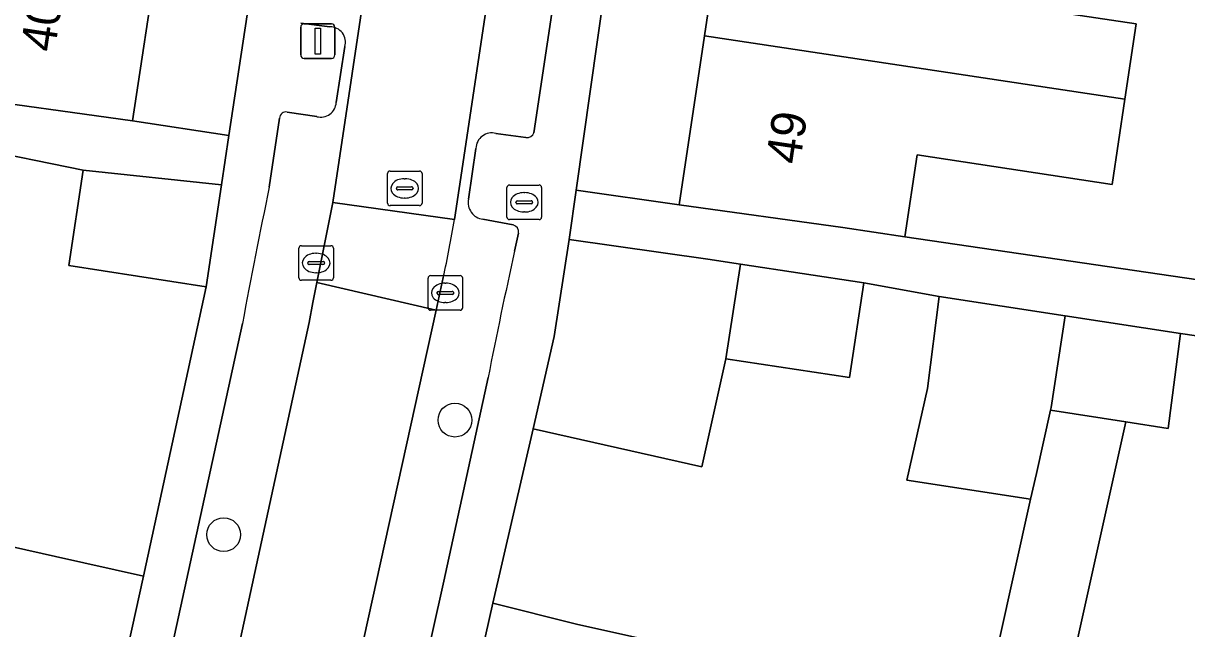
# Model space of a CAD drawing. Extents: x 162172 to 163187, y 382874 to 383685.
# Drawn here: x 163018.49 to 163052.14, y 383120.38 to 383137.87 of the extents above; entities that cross this region are included whole.
import ezdxf

# ---------------------------------------------------------------- set-up
doc = ezdxf.new("R2010")
doc.units = 0
for name, color, linetype in [('IMGEO_Boom', 7, 'Continuous'), ('IMGEO_Brandkraan', 7, 'Continuous'), ('IMGEO_Erf', 7, 'Continuous'), ('IMGEO_Kolk', 7, 'Continuous'), ('IMGEO_Lichtmast', 7, 'Continuous'), ('IMGEO_Muur', 7, 'Continuous'), ('IMGEO_Pand', 7, 'Continuous'), ('IMGEO_Pand_nummerreeks', 7, 'Continuous'), ('IMGEO_Parkeervlak_open', 7, 'Continuous'), ('IMGEO_Rijbaan_lokaal_open', 7, 'Continuous'), ('IMGEO_Rioolput', 7, 'Continuous'), ('IMGEO_Voetpad_open', 7, 'Continuous')]:
    doc.layers.add(name, color=color, linetype=linetype)

msp = doc.modelspace()

# ---------------------------------------------------------------- linework, layer by layer
at = {"layer": 'IMGEO_Boom'}
for centre in [(163030.975, 383126.407), (163024.288, 383123.097)]:
    msp.add_circle(centre, 0.489, dxfattribs=at)
at = {"layer": 'IMGEO_Brandkraan'}
for p, q in [((163032.479, 383132.274), (163032.479, 383133.126)), ((163032.554, 383133.2), (163033.406, 383133.2)), ((163032.967, 383132.98), (163032.992, 383132.98)), ((163033.48, 383133.126), (163033.48, 383132.274)), ((163032.738, 383132.694), (163032.738, 383132.706)), ((163033.176, 383132.657), (163032.778, 383132.657)), ((163032.781, 383132.743), (163033.179, 383132.743)), ((163033.222, 383132.706), (163033.222, 383132.694)), ((163032.99, 383132.42), (163032.965, 383132.42)), ((163033.406, 383132.2), (163032.554, 383132.2))]:
    msp.add_line(p, q, dxfattribs=at)
for points in [[(163032.479, 383132.274), (163032.479, 383133.126)], [(163032.554, 383133.2), (163033.406, 383133.2)], [(163033.48, 383133.126), (163033.48, 383132.274)], [(163033.406, 383132.2), (163032.554, 383132.2)]]:
    msp.add_lwpolyline(points, dxfattribs=at)
for centre, radius, start, end in [((163032.556, 383133.124), 0.0765, 91.552, 178.448), ((163032.556, 383133.124), 0.0765, 91.552, 178.448), ((163033.404, 383133.124), 0.0765, 1.552, 88.448), ((163033.404, 383133.124), 0.0765, 1.552, 88.448), ((163032.778, 383132.703), 0.0403, 85.8775, 175.7526), ((163032.775, 383132.693), 0.0366, 178.938, 274.7102), ((163033.179, 383132.7), 0.043, 264.8664, 352.4533), ((163033.183, 383132.705), 0.0386, 1.7309, 96.639), ((163032.556, 383132.276), 0.0765, 181.552, 268.448), ((163032.556, 383132.276), 0.0765, 181.552, 268.448), ((163033.404, 383132.276), 0.0765, 271.552, 358.448), ((163033.404, 383132.276), 0.0765, 271.552, 358.448)]:
    msp.add_arc(centre, radius, start, end, dxfattribs=at)
for centre, major_axis, ratio, start_param, end_param in [((163032.966, 383132.7), (-0.387, 0.002), 0.722429, 4.712389, 7.853982), ((163032.991, 383132.7), (-0.39, 0.002), 0.717154, 1.570796, 4.712389)]:
    msp.add_ellipse(centre, major_axis=major_axis, ratio=ratio, start_param=start_param, end_param=end_param, dxfattribs=at)
at = {"layer": 'IMGEO_Erf'}
for points in [[(163039.037, 383230.674), (163036.097, 383231.121), (163035.35, 383226.153), (163034.641, 383221.439), (163033.933, 383216.725), (163033.224, 383212.011), (163032.515, 383207.297), (163031.806, 383202.583), (163031.098, 383197.869), (163030.389, 383193.155), (163029.68, 383188.442), (163028.748, 383182.244), (163028.04, 383177.53), (163027.331, 383172.817), (163026.622, 383168.103), (163025.913, 383163.389), (163025.205, 383158.674), (163024.496, 383153.961), (163023.787, 383149.247), (163023.078, 383144.532), (163022.37, 383139.819), (163021.653, 383135.053), (163024.437, 383134.63)], [(163047.622, 383124.122), (163044.042, 383124.672), (163044.637, 383127.317), (163044.981, 383129.981), (163042.797, 383130.377), (163042.384, 383127.642), (163038.812, 383128.181), (163038.11, 383125.06), (163033.233, 383126.158), (163032.072, 383121.12), (163034.487, 383120.513), (163036.871, 383119.984), (163039.136, 383119.482), (163037.909, 383113.95), (163040.271, 383113.426), (163041.077, 383117.068), (163043.222, 383116.593), (163043.641, 383118.483), (163046.121, 383117.933), (163046.242, 383117.906)], [(163056.356, 383120.39), (163056.667, 383122.937), (163057.043, 383122.891), (163057.448, 383125.312), (163053.935, 383125.826), (163054.391, 383128.555), (163051.953, 383128.911), (163051.599, 383126.167), (163050.37, 383126.356), (163049.947, 383124.452), (163048.389, 383117.431), (163047.161, 383111.899), (163049.522, 383111.376), (163051.755, 383110.881), (163052.984, 383116.412), (163053.364, 383118.123), (163055.75, 383117.593)]]:
    msp.add_lwpolyline(points, close=True, dxfattribs=at)
for points in [[(163037.149, 383151.861), (163034.477, 383133.054), (163037.462, 383132.63), (163038.189, 383137.51), (163038.89, 383142.22)], [(163045.037, 383138.705), (163050.673, 383137.856), (163050.346, 383135.679), (163049.976, 383133.218), (163044.339, 383134.068), (163043.983, 383131.701), (163057.99, 383129.648), (163058.091, 383130.579), (163055.442, 383130.893), (163055.877, 383134.562), (163058.943, 383134.199), (163059.146, 383135.906), (163056.419, 383136.285), (163056.859, 383139.456)], [(163016.924, 383123.028), (163019.425, 383122.469), (163021.966, 383121.901), (163023.786, 383130.253), (163019.809, 383130.877), (163020.226, 383133.633), (163017.008, 383134.284)]]:
    msp.add_lwpolyline(points, dxfattribs=at)
at = {"layer": 'IMGEO_Kolk'}
for p, q in [((163026.462, 383130.52), (163026.462, 383131.372)), ((163026.537, 383131.446), (163027.389, 383131.446)), ((163027.463, 383131.372), (163027.463, 383130.52)), ((163026.721, 383130.94), (163026.721, 383130.952)), ((163026.764, 383130.989), (163027.162, 383130.989)), ((163026.95, 383131.226), (163026.975, 383131.226)), ((163027.205, 383130.952), (163027.205, 383130.94)), ((163027.159, 383130.903), (163026.761, 383130.903)), ((163026.973, 383130.666), (163026.948, 383130.666)), ((163030.272, 383130.582), (163031.124, 383130.582)), ((163027.389, 383130.446), (163026.537, 383130.446)), ((163030.197, 383129.656), (163030.197, 383130.508)), ((163030.685, 383130.362), (163030.71, 383130.362)), ((163031.198, 383130.508), (163031.198, 383129.656)), ((163030.456, 383130.076), (163030.456, 383130.088)), ((163030.894, 383130.039), (163030.496, 383130.039)), ((163030.499, 383130.125), (163030.897, 383130.125)), ((163030.94, 383130.088), (163030.94, 383130.076)), ((163031.124, 383129.582), (163030.272, 383129.582)), ((163030.708, 383129.802), (163030.683, 383129.802))]:
    msp.add_line(p, q, dxfattribs=at)
for points in [[(163026.462, 383130.52), (163026.462, 383131.372)], [(163026.537, 383131.446), (163027.389, 383131.446)], [(163027.463, 383131.372), (163027.463, 383130.52)], [(163030.272, 383130.582), (163031.124, 383130.582)], [(163027.389, 383130.446), (163026.537, 383130.446)], [(163030.197, 383129.656), (163030.197, 383130.508)], [(163031.198, 383130.508), (163031.198, 383129.656)], [(163031.124, 383129.582), (163030.272, 383129.582)]]:
    msp.add_lwpolyline(points, dxfattribs=at)
for centre, radius, start, end in [((163026.539, 383131.37), 0.0765, 91.552, 178.448), ((163026.539, 383131.37), 0.0765, 91.552, 178.448), ((163027.387, 383131.37), 0.0765, 1.552, 88.448), ((163027.387, 383131.37), 0.0765, 1.552, 88.448), ((163026.761, 383130.949), 0.0403, 85.8775, 175.7526), ((163026.758, 383130.939), 0.0366, 178.938, 274.7102), ((163027.162, 383130.946), 0.043, 264.8664, 352.4533), ((163027.166, 383130.951), 0.0386, 1.7309, 96.639), ((163030.274, 383130.506), 0.0765, 91.552, 178.448), ((163030.274, 383130.506), 0.0765, 91.552, 178.448), ((163031.122, 383130.506), 0.0765, 1.552, 88.448), ((163031.122, 383130.506), 0.0765, 1.552, 88.448), ((163026.539, 383130.522), 0.0765, 181.552, 268.448), ((163026.539, 383130.522), 0.0765, 181.552, 268.448), ((163027.387, 383130.522), 0.0765, 271.552, 358.448), ((163027.387, 383130.522), 0.0765, 271.552, 358.448), ((163030.496, 383130.085), 0.0403, 85.8775, 175.7526), ((163030.493, 383130.075), 0.0366, 178.938, 274.7102), ((163030.897, 383130.082), 0.043, 264.8664, 352.4533), ((163030.901, 383130.087), 0.0386, 1.7309, 96.639), ((163030.274, 383129.658), 0.0765, 181.552, 268.448), ((163030.274, 383129.658), 0.0765, 181.552, 268.448), ((163031.122, 383129.658), 0.0765, 271.552, 358.448), ((163031.122, 383129.658), 0.0765, 271.552, 358.448)]:
    msp.add_arc(centre, radius, start, end, dxfattribs=at)
for centre, major_axis, ratio, start_param, end_param in [((163026.949, 383130.946), (-0.387, 0.002), 0.722429, 4.712389, 7.853982), ((163026.974, 383130.946), (-0.39, 0.002), 0.717154, 1.570796, 4.712389), ((163030.684, 383130.082), (-0.387, 0.002), 0.722429, 4.712389, 7.853982), ((163030.709, 383130.082), (-0.39, 0.002), 0.717154, 1.570796, 4.712389)]:
    msp.add_ellipse(centre, major_axis=major_axis, ratio=ratio, start_param=start_param, end_param=end_param, dxfattribs=at)
at = {"layer": 'IMGEO_Lichtmast'}
for p, q in [((163026.515, 383136.957), (163026.515, 383137.757)), ((163026.515, 383137.757), (163026.515, 383136.957)), ((163026.615, 383137.857), (163027.405, 383137.857)), ((163027.405, 383137.857), (163026.615, 383137.857)), ((163027.505, 383137.757), (163027.505, 383136.957)), ((163027.505, 383136.957), (163027.505, 383137.757)), ((163027.405, 383136.857), (163026.615, 383136.857)), ((163026.615, 383136.857), (163027.405, 383136.857))]:
    msp.add_line(p, q, dxfattribs=at)
msp.add_lwpolyline([(163026.935, 383137.732), (163027.085, 383137.732), (163027.085, 383136.982), (163026.935, 383136.982), (163026.935, 383137.732)], dxfattribs=at)
for centre, start, end in [((163026.615, 383137.757), 90, 180), ((163026.615, 383137.757), 90, 180), ((163027.405, 383137.757), 0, 90), ((163027.405, 383137.757), 360, 90), ((163026.615, 383136.957), 180, 270), ((163026.615, 383136.957), 180, 270), ((163027.405, 383136.957), 270, 0), ((163027.405, 383136.957), 270, 0)]:
    msp.add_arc(centre, 0.1, start, end, dxfattribs=at)
at = {"layer": 'IMGEO_Muur'}
for points in [[(163021.966, 383121.901), (163023.786, 383130.253)], [(163033.847, 383128.823), (163032.072, 383121.12)]]:
    msp.add_lwpolyline(points, dxfattribs=at)
at = {"layer": 'IMGEO_Pand'}
for points in [[(163038.189, 383137.51), (163048.359, 383135.978), (163050.346, 383135.679), (163050.673, 383137.856), (163045.037, 383138.705), (163045.418, 383141.237), (163038.89, 383142.22)], [(163022.37, 383139.819), (163011.949, 383141.4), (163008.057, 383141.991), (163007.702, 383139.65), (163009.428, 383139.389), (163015.064, 383138.536), (163014.686, 383136.04), (163016.505, 383135.765), (163021.653, 383135.053)], [(163038.189, 383137.51), (163037.462, 383132.63), (163042.188, 383131.971), (163043.983, 383131.701), (163044.339, 383134.068), (163049.976, 383133.218), (163050.346, 383135.679), (163048.359, 383135.978)], [(163023.786, 383130.253), (163024.221, 383133.207), (163020.226, 383133.633), (163019.809, 383130.877)], [(163039.228, 383130.915), (163038.285, 383131.057), (163034.275, 383131.629), (163033.847, 383128.823), (163033.233, 383126.158), (163038.11, 383125.06), (163038.812, 383128.181)], [(163039.228, 383130.915), (163038.812, 383128.181), (163042.384, 383127.642), (163042.797, 383130.377)], [(163048.617, 383129.423), (163044.981, 383129.981), (163044.637, 383127.317), (163044.042, 383124.672), (163047.622, 383124.122), (163047.788, 383124.865), (163048.197, 383126.69), (163048.214, 383126.768)], [(163051.953, 383128.911), (163048.617, 383129.423), (163048.214, 383126.768), (163048.197, 383126.69), (163050.37, 383126.356), (163051.599, 383126.167)], [(163049.947, 383124.452), (163050.37, 383126.356), (163048.197, 383126.69), (163047.788, 383124.865), (163047.622, 383124.122), (163046.242, 383117.906), (163048.389, 383117.431)], [(163021.966, 383121.901), (163019.425, 383122.469), (163016.924, 383123.028), (163016.681, 383121.931), (163016.039, 383122.074), (163015.403, 383119.196), (163013.791, 383111.904), (163018.734, 383110.811), (163019.497, 383110.642)], [(163036.871, 383119.984), (163034.487, 383120.513), (163032.072, 383121.12), (163029.271, 383108.675), (163029.069, 383108.732), (163029.019, 383108.524), (163029.377, 383108.445), (163034.087, 383107.405), (163036.418, 383117.937)]]:
    msp.add_lwpolyline(points, close=True, dxfattribs=at)
at = {"layer": 'IMGEO_Parkeervlak_open'}
for points in [[(163052.957, 383278.34), (163045.786, 383230.678), (163045.636, 383229.68), (163045.404, 383228.141), (163038.236, 383180.621), (163037.85, 383178.065), (163037.751, 383177.408), (163031.1, 383133.102), (163030.962, 383132.202)], [(163022.495, 383109.64), (163026.76, 383129.231), (163026.869, 383129.807), (163026.979, 383130.383), (163027.448, 383132.692), (163031.942, 383162.715), (163034.322, 383178.584), (163034.707, 383181.151), (163034.878, 383182.293), (163041.863, 383228.565)], [(163033.26, 383134.711), (163036.974, 383159.441)], [(163026.518, 383137.873), (163027.36, 383137.767)], [(163027.79, 383137.198), (163027.543, 383135.586)], [(163026.981, 383135.175), (163026.126, 383135.306)], [(163025.903, 383135.133), (163025.606, 383133.142)], [(163032.162, 383134.687), (163033.027, 383134.574)], [(163031.368, 383132.791), (163031.583, 383134.258)], [(163032.662, 383132.052), (163031.779, 383132.209)], [(163032.701, 383131.292), (163032.817, 383131.812)], [(163030.638, 383130.526), (163030.43, 383129.579), (163025.877, 383108.905)], [(163024.831, 383129.199), (163020.785, 383110.656)], [(163027.854, 383109.222), (163030.658, 383121.75), (163031.935, 383127.642)]]:
    msp.add_lwpolyline(points, dxfattribs=at)
for centre, radius, start, end in [((163027.37, 383137.328), 0.44, 342.8483, 91.3092), ((163026.088, 383135.125), 0.185, 78.1295, 177.478), ((163027.09, 383135.615), 0.454, 256.0364, 356.3208), ((163032.038, 383134.25), 0.455, 74.1332, 178.9387), ((163033.058, 383134.789), 0.217, 261.8704, 339.0392), ((163254.722, 383086.061), 233.904, 168.38804, 169.37239), ((163031.847, 383132.693), 0.489, 168.4081, 262.0503), ((162997.088, 383137.881), 34.347, 347.6348, 350.4826), ((163032.591, 383131.836), 0.227, 353.8638, 71.8476), ((163174.454, 383099.638), 145.244, 167.41211, 168.88336)]:
    msp.add_arc(centre, radius, start, end, dxfattribs=at)
at = {"layer": 'IMGEO_Rijbaan_lokaal_open'}
for points in [[(163037.751, 383177.408), (163037.85, 383178.065), (163034.322, 383178.584), (163031.942, 383162.715), (163027.448, 383132.692), (163030.962, 383132.202), (163031.1, 383133.102)], [(163030.43, 383129.579), (163026.979, 383130.383), (163026.869, 383129.807), (163026.76, 383129.231), (163022.495, 383109.64), (163021.691, 383106.09), (163025.113, 383105.327), (163025.877, 383108.905)]]:
    msp.add_lwpolyline(points, close=True, dxfattribs=at)
msp.add_lwpolyline([(163030.962, 383132.202), (163027.448, 383132.692), (163026.979, 383130.383), (163030.43, 383129.579), (163030.638, 383130.526)], dxfattribs=at)
msp.add_arc((162997.088, 383137.881), 34.347, 347.6348, 350.4826, dxfattribs=at)
at = {"layer": 'IMGEO_Rioolput'}
for p, q in [((163029.098, 383133.603), (163029.95, 383133.603)), ((163029.023, 383132.677), (163029.023, 383133.529)), ((163029.511, 383133.383), (163029.536, 383133.383)), ((163030.024, 383133.529), (163030.024, 383132.677)), ((163029.282, 383133.097), (163029.282, 383133.109)), ((163029.72, 383133.06), (163029.322, 383133.06)), ((163029.325, 383133.146), (163029.723, 383133.146)), ((163029.766, 383133.109), (163029.766, 383133.097)), ((163029.95, 383132.603), (163029.098, 383132.603)), ((163029.534, 383132.823), (163029.509, 383132.823))]:
    msp.add_line(p, q, dxfattribs=at)
for points in [[(163029.098, 383133.603), (163029.95, 383133.603)], [(163029.023, 383132.677), (163029.023, 383133.529)], [(163030.024, 383133.529), (163030.024, 383132.677)], [(163029.95, 383132.603), (163029.098, 383132.603)]]:
    msp.add_lwpolyline(points, dxfattribs=at)
for centre, radius, start, end in [((163029.1, 383133.527), 0.0765, 91.552, 178.448), ((163029.1, 383133.527), 0.0765, 91.552, 178.448), ((163029.948, 383133.527), 0.0765, 1.552, 88.448), ((163029.948, 383133.527), 0.0765, 1.552, 88.448), ((163029.322, 383133.106), 0.0403, 85.8775, 175.7526), ((163029.319, 383133.096), 0.0366, 178.938, 274.7102), ((163029.723, 383133.103), 0.043, 264.8664, 352.4533), ((163029.727, 383133.108), 0.0386, 1.7309, 96.639), ((163029.1, 383132.679), 0.0765, 181.552, 268.448), ((163029.1, 383132.679), 0.0765, 181.552, 268.448), ((163029.948, 383132.679), 0.0765, 271.552, 358.448), ((163029.948, 383132.679), 0.0765, 271.552, 358.448)]:
    msp.add_arc(centre, radius, start, end, dxfattribs=at)
for centre, major_axis, ratio, start_param, end_param in [((163029.51, 383133.103), (-0.387, 0.002), 0.722429, 4.712389, 7.853982), ((163029.535, 383133.103), (-0.39, 0.002), 0.717154, 1.570796, 4.712389)]:
    msp.add_ellipse(centre, major_axis=major_axis, ratio=ratio, start_param=start_param, end_param=end_param, dxfattribs=at)
at = {"layer": 'IMGEO_Voetpad_open'}
for points in [[(163043.453, 383259.501), (163043.302, 383258.58), (163042.291, 383251.846), (163041.773, 383248.496), (163041.692, 383247.97), (163039.68, 383234.953), (163039.263, 383232.162), (163039.037, 383230.674), (163024.437, 383134.63), (163024.221, 383133.207), (163023.786, 383130.253), (163021.966, 383121.901), (163019.497, 383110.642), (163018.734, 383110.811), (163018.493, 383109.759)], [(163029.245, 383108.188), (163029.377, 383108.445), (163029.019, 383108.524), (163029.069, 383108.732), (163029.271, 383108.675), (163032.072, 383121.12), (163033.233, 383126.158), (163033.847, 383128.823), (163034.275, 383131.629), (163034.476, 383133.047), (163034.477, 383133.054), (163037.149, 383151.861), (163051.971, 383250)], [(163036.974, 383159.441), (163033.26, 383134.711)], [(162996.669, 383138.332), (162998.582, 383136.984), (163002.231, 383136.441), (163005.806, 383135.909), (163005.768, 383135.654), (163009.828, 383135.047), (163009.864, 383135.364), (163013.6, 383134.799), (163017.008, 383134.284), (163020.226, 383133.633), (163024.221, 383133.207), (163024.437, 383134.63), (163021.653, 383135.053), (163016.505, 383135.765), (163014.686, 383136.04), (162999.585, 383138.494)], [(163027.36, 383137.767), (163026.518, 383137.873)], [(163027.543, 383135.586), (163027.79, 383137.198)], [(163026.126, 383135.306), (163026.981, 383135.175)], [(163025.606, 383133.142), (163025.903, 383135.133)], [(163033.027, 383134.574), (163032.162, 383134.687)], [(163031.583, 383134.258), (163031.368, 383132.791)], [(163057.99, 383129.648), (163043.983, 383131.701), (163042.188, 383131.971), (163037.462, 383132.63), (163034.477, 383133.054), (163034.476, 383133.047), (163034.275, 383131.629), (163038.285, 383131.057), (163039.228, 383130.915), (163042.797, 383130.377), (163044.981, 383129.981), (163048.617, 383129.423), (163051.953, 383128.911), (163054.391, 383128.555)], [(163031.779, 383132.209), (163032.662, 383132.052)], [(163032.817, 383131.812), (163032.701, 383131.292)], [(163020.785, 383110.656), (163024.831, 383129.199)], [(163031.935, 383127.642), (163030.658, 383121.75), (163027.854, 383109.222)]]:
    msp.add_lwpolyline(points, dxfattribs=at)
for centre, radius, start, end in [((163027.37, 383137.328), 0.44, 342.8483, 91.3092), ((163026.088, 383135.125), 0.185, 78.1295, 177.478), ((163027.09, 383135.615), 0.454, 256.0364, 356.3208), ((163032.038, 383134.25), 0.455, 74.1332, 178.9387), ((163033.058, 383134.789), 0.217, 261.8704, 339.0392), ((163254.722, 383086.061), 233.904, 168.38804, 169.37239), ((163031.847, 383132.693), 0.489, 168.4081, 262.0503), ((163032.591, 383131.836), 0.227, 353.8638, 71.8476), ((163174.454, 383099.638), 145.244, 167.41211, 168.88336)]:
    msp.add_arc(centre, radius, start, end, dxfattribs=at)

# ---------------------------------------------------------------- texts
at = {"layer": 'IMGEO_Pand_nummerreeks'}
for s, rotation, p in [('40', 81.4495, (163019.4, 383137.015)), ('49', 81.5287, (163040.948, 383133.77))]:
    msp.add_text(s, height=1, rotation=rotation, dxfattribs=at).set_placement(p)

doc.saveas('drawing.dxf')
